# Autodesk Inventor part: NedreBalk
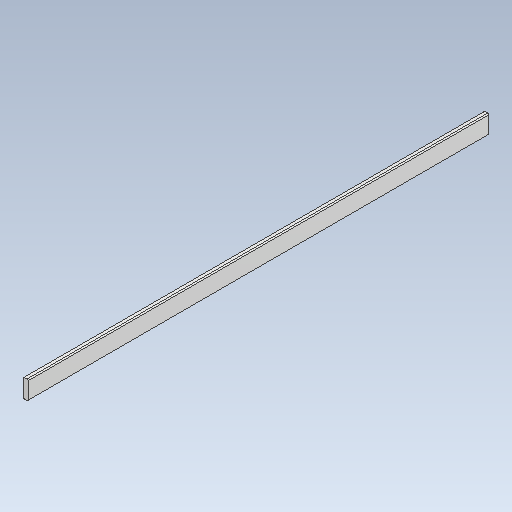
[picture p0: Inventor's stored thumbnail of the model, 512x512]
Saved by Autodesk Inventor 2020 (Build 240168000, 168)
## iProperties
Created: 2019-06
Part Number: NedreBalk
Material: Aluminum
Document SubType Name: Modeling
Designer: cl
Density: 2.7 g/cm^3
Appearance: Satin
Author: cl
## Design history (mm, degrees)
sketch "Sketch1"
  geometry: L1 (0, 0)-(7, 0); L2 (12, -5)-(12, -85); L3 (7, -90)-(0, -90); L4 (0, 0)-(0, -90); L5 (0, 0)-(-7, 0); L6 (-12, -5)-(-12, -85); L7 (-7, -90)-(0, -90); A1 r 5 centre (7, -5) between (12, -5) and (7, 0); A2 r 5 centre (7, -85) between (7, -90) and (12, -85); A3 r 5 centre (-7, -5) between (-7, 0) and (-12, -5); A4 r 5 centre (-7, -85) between (-12, -85) and (-7, -90); 4 further points
  constraints: 14 end point, 8 point on circle, 8 point on line, 8 symmetric about line, 4 centre point, 4 tangent, 2 perpendicular, 1 equal radius, 1 horizontal, 1 vertical, 2 other
  dimensions: "d0" = 12 distance of L1.start point (12, 0); "d1" = 90 distance of point (12, 0) point (12, -90); "d2" = 5 radius of A1
extrude "Extrusion1" new body sketch "Sketch1" distance "d3" = 2192 (computed from Dagbredd); taper "d4" = 0 deg
body "Solid1"
other parameters: "Daghöjd" = 3254, "Dagbredd" = 2222
